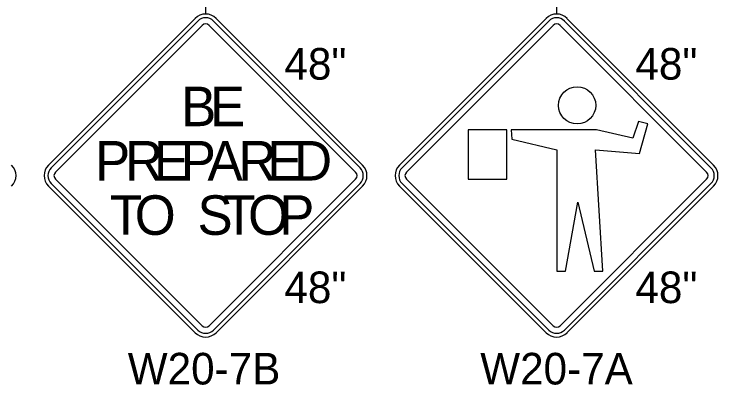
# Model space of a CAD drawing. Extents: x 99999.1 to 100095.7, y 99995 to 100010.7.
# Drawn here: x 100042.24 to 100043.845, y 100004.648 to 100005.492 of the extents above; entities that cross this region are included whole.
import ezdxf

# ---------------------------------------------------------------- set-up
doc = ezdxf.new("R2010")
doc.units = 0
doc.layers.add('TR_SN_ConstructionSigns', color=7, linetype='Continuous')
doc.layers.add('TR_WZ_WorkZoneDetails', color=7, linetype='Continuous')

msp = doc.modelspace()

# ---------------------------------------------------------------- linework, layer by layer
at = {"layer": 'TR_SN_ConstructionSigns'}
for p, q in [((100042.6528, 100005.4824), (100042.3187, 100005.1483)), ((100042.6588, 100005.4765), (100042.3246, 100005.1424)), ((100043.0287, 100005.1424), (100042.6945, 100005.4765)), ((100043.0346, 100005.1483), (100042.7005, 100005.4824)), ((100043.4528, 100005.4824), (100043.1187, 100005.1483)), ((100043.4588, 100005.4765), (100043.1246, 100005.1424)), ((100043.8287, 100005.1424), (100043.4945, 100005.4765)), ((100043.8346, 100005.1483), (100043.5005, 100005.4824)), ((100042.3346, 100005.1324), (100042.6687, 100005.4665)), ((100042.6846, 100005.4665), (100043.0187, 100005.1324)), ((100043.1346, 100005.1324), (100043.4687, 100005.4665)), ((100043.4846, 100005.4665), (100043.8187, 100005.1324)), ((100042.3246, 100005.1066), (100042.6588, 100004.7725)), ((100042.6687, 100004.7824), (100042.3346, 100005.1165)), ((100043.0187, 100005.1165), (100042.6846, 100004.7824)), ((100042.6945, 100004.7725), (100043.0287, 100005.1066)), ((100043.1246, 100005.1066), (100043.4588, 100004.7725)), ((100043.4687, 100004.7824), (100043.1346, 100005.1165)), ((100043.8187, 100005.1165), (100043.4846, 100004.7824)), ((100043.4945, 100004.7725), (100043.8287, 100005.1066)), ((100042.3187, 100005.1006), (100042.6528, 100004.7665)), ((100042.7005, 100004.7665), (100043.0346, 100005.1006)), ((100043.1187, 100005.1006), (100043.4528, 100004.7665)), ((100043.5005, 100004.7665), (100043.8346, 100005.1006))]:
    msp.add_line(p, q, dxfattribs=at)
for points in [[(100043.3733, 100005.2289), (100043.3746, 100005.2072), (100043.4772, 100005.1833), (100043.4772, 100004.907), (100043.4972, 100004.907), (100043.5253, 100005.064), (100043.5628, 100004.907), (100043.5819, 100004.907), (100043.5652, 100005.1832), (100043.6655, 100005.1751), (100043.6844, 100005.2421), (100043.6637, 100005.248), (100043.6505, 100005.2097), (100043.5676, 100005.2289)], [(100043.2754, 100005.2286), (100043.2754, 100005.1164), (100043.363, 100005.1164), (100043.363, 100005.2286)]]:
    msp.add_lwpolyline(points, close=True, dxfattribs=at)
msp.add_circle((100043.5236, 100005.2844), 0.0424, dxfattribs=at)
for centre, radius, start, end in [((100042.6767, 100005.4586), 0.0338, 45, 135), ((100043.4767, 100005.4586), 0.0338, 45, 135), ((100042.6767, 100005.4586), 0.0253, 45, 135), ((100043.4767, 100005.4586), 0.0253, 45, 135), ((100042.6767, 100005.4586), 0.0113, 45, 135), ((100043.4767, 100005.4586), 0.0113, 45, 135), ((100042.2108, 100005.1245), 0.0338, 315, 45), ((100042.3425, 100005.1245), 0.0338, 135, 225), ((100042.3425, 100005.1245), 0.0253, 135, 225), ((100043.0108, 100005.1245), 0.0253, 315, 45), ((100043.0108, 100005.1245), 0.0338, 315, 45), ((100043.1425, 100005.1245), 0.0338, 135, 225), ((100043.1425, 100005.1245), 0.0253, 135, 225), ((100043.8108, 100005.1245), 0.0253, 315, 45), ((100043.8108, 100005.1245), 0.0338, 315, 45), ((100042.3425, 100005.1245), 0.0113, 135, 225), ((100043.0108, 100005.1245), 0.0113, 315, 45), ((100043.1425, 100005.1245), 0.0113, 135, 225), ((100043.8108, 100005.1245), 0.0113, 315, 45), ((100042.6767, 100004.7904), 0.0253, 225, 315), ((100042.6767, 100004.7904), 0.0113, 225, 315), ((100043.4767, 100004.7904), 0.0253, 225, 315), ((100043.4767, 100004.7904), 0.0113, 225, 315), ((100042.6767, 100004.7904), 0.0338, 225, 315), ((100043.4767, 100004.7904), 0.0338, 225, 315)]:
    msp.add_arc(centre, radius, start, end, dxfattribs=at)
at = {"layer": 'TR_WZ_WorkZoneDetails'}
for p, q in [((100042.6767, 100005.7323), (100042.6767, 100005.4923)), ((100043.4767, 100005.7323), (100043.4767, 100005.4923))]:
    msp.add_line(p, q, dxfattribs=at)

# ---------------------------------------------------------------- texts
at = {"layer": 'TR_SN_ConstructionSigns'}
for s, p in [('48"', (100042.8564, 100005.343)), ('48"', (100043.6564, 100005.343)), ('48"', (100042.8564, 100004.8339)), ('48"', (100043.6564, 100004.8339)), ('W20-7B', (100042.4993, 100004.6486)), ('W20-7A', (100043.3027, 100004.6486))]:
    msp.add_text(s, height=0.072, rotation=360, dxfattribs=at).set_placement(p)
for s, p in [('B', (100042.6209, 100005.237)), ('E', (100042.6866, 100005.237)), ('P', (100042.4247, 100005.1132)), ('R', (100042.4931, 100005.1132)), ('E', (100042.5588, 100005.1132)), ('P', (100042.62, 100005.1132)), ('A', (100042.6812, 100005.1132)), ('R', (100042.7514, 100005.1132)), ('E', (100042.8171, 100005.1132)), ('D', (100042.8783, 100005.1132)), ('T', (100042.4584, 100004.9895)), ('O', (100042.5151, 100004.9895)), ('S', (100042.6582, 100004.9895)), ('T', (100042.7167, 100004.9895)), ('O', (100042.7734, 100004.9895)), ('P', (100042.8445, 100004.9895))]:
    msp.add_text(s, height=0.09, dxfattribs=at).set_placement(p)

doc.saveas('drawing.dxf')
